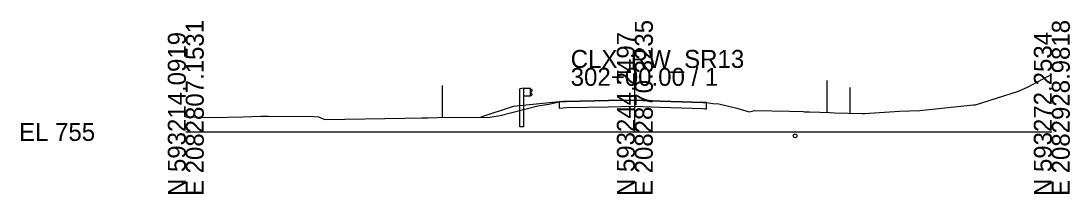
# Model space of a CAD drawing. Extents: x -26 to 2138, y -10 to 4518.
# Drawn here: x -25.7 to 137.8, y 1490.3 to 1517.3 of the extents above; entities that cross this region are included whole.
import ezdxf

# ---------------------------------------------------------------- set-up
doc = ezdxf.new("R2010")
doc.units = 0
for name, color, linetype in [('GK_Cells', 7, 'Continuous'), ('MD_X_Asphalt_Pavement', 7, 'Continuous'), ('RD_P_Cells', 7, 'Continuous'), ('RW_P_Esmt_SH', 7, 'Continuous'), ('RW_X_Esmt_SH', 7, 'Continuous'), ('UT_X_Water', 7, 'Continuous'), ('XS_P_Finished_Grade', 7, 'Continuous'), ('XS_X_Ground_Line', 7, 'Continuous')]:
    doc.layers.add(name, color=color, linetype=linetype)

msp = doc.modelspace()

# ---------------------------------------------------------------- linework, layer by layer
at = {"layer": 'GK_Cells'}
for p, q in [((70, 1500), (70, 1510)), ((0, 1500), (70, 1500)), ((70, 1500), (135, 1500))]:
    msp.add_line(p, q, dxfattribs=at)
at = {"layer": 'MD_X_Asphalt_Pavement'}
msp.add_lwpolyline([(58.83, 1504.74), (58.21, 1504.69), (58.21, 1503.73), (58.83, 1503.78), (59.27, 1503.8), (65.9, 1503.94), (69.89, 1504.02), (73.96, 1503.86), (80.6, 1503.64), (80.91, 1503.63), (81.15, 1503.62), (81.15, 1504.58), (80.91, 1504.59), (80.6, 1504.6), (73.96, 1504.82), (69.89, 1504.97), (65.9, 1504.9), (59.27, 1504.76), (58.83, 1504.74)], dxfattribs=at)
at = {"layer": 'RD_P_Cells'}
for p, q in [((52.1, 1506.73), (52.05, 1506.71)), ((52.05, 1500.81), (52.05, 1506.71)), ((52.64, 1506.81), (52.1, 1506.73)), ((52.72, 1506.77), (52.64, 1506.81)), ((53.72, 1506.77), (52.72, 1506.77)), ((52.72, 1500.81), (52.72, 1506.77)), ((53.72, 1505.58), (53.72, 1506.77)), ((53.81, 1506.67), (53.72, 1506.68)), ((53.73, 1506.17), (53.73, 1506.22)), ((53.73, 1506.13), (53.73, 1506.17)), ((53.76, 1506.28), (53.97, 1506.43)), ((53.97, 1506.56), (53.81, 1506.67)), ((53.72, 1505.58), (52.72, 1505.58)), ((53.72, 1505.66), (53.81, 1505.68)), ((53.97, 1505.92), (53.76, 1506.06)), ((53.81, 1505.68), (53.97, 1505.79)), ((52.72, 1500.81), (52.05, 1500.81))]:
    msp.add_line(p, q, dxfattribs=at)
for points in [[(53.74, 1506.23), (53.74, 1506.11), (53.73, 1506.11), (53.73, 1506.23)], [(53.74, 1506.2), (53.74, 1506.14), (53.76, 1506.14), (53.76, 1506.2)]]:
    msp.add_lwpolyline(points, close=True, dxfattribs=at)
for centre, start, end in [((53.81, 1506.22), 124.962, 180), ((53.92, 1506.49), 304.962, 54.7677), ((53.81, 1506.13), 180, 235.038), ((53.92, 1505.86), 304.962, 54.7677)]:
    msp.add_arc(centre, 0.0781, start, end, dxfattribs=at)
at = {"layer": 'RW_P_Esmt_SH'}
msp.add_line((103.56, 1502.94), (103.56, 1506.94), dxfattribs=at)
at = {"layer": 'RW_X_Esmt_SH'}
for p, q in [((100, 1503.05), (100, 1508.05)), ((40, 1502.24), (40, 1507.24))]:
    msp.add_line(p, q, dxfattribs=at)
at = {"layer": 'UT_X_Water'}
msp.add_circle((95, 1499.4), 0.3, dxfattribs=at)
at = {"layer": 'XS_P_Finished_Grade'}
for p, q in [((58.21, 1504.69), (51.05, 1503.97)), ((51.05, 1503.97), (46, 1502.29))]:
    msp.add_line(p, q, dxfattribs=at)
at = {"layer": 'XS_X_Ground_Line'}
msp.add_lwpolyline([(0, 1502.38), (1.9, 1502.3), (4.01, 1502.26), (8.93, 1502.36), (11.7, 1502.45), (12.88, 1502.46), (19.98, 1502.43), (20.67, 1502.35), (21.65, 1501.93), (34.16, 1502.14), (36.73, 1502.19), (37.13, 1502.19), (37.71, 1502.2), (39.2, 1502.23), (47.4, 1502.3), (49, 1502.55), (50.61, 1502.96), (54.9, 1504.08), (56.58, 1504.34), (58.21, 1504.69), (58.83, 1504.74), (59.27, 1504.76), (65.9, 1504.9), (69.89, 1504.97), (73.96, 1504.82), (80.6, 1504.6), (80.91, 1504.59), (81.15, 1504.58), (82.16, 1504.43), (83.09, 1504.41), (85.9, 1503.69), (87.8, 1503.13), (88.3, 1503.25), (88.64, 1503.33), (94.13, 1503.23), (96.25, 1503.17), (96.44, 1503.16), (97.24, 1503.14), (100.43, 1503.04), (101.15, 1503.01), (105.45, 1502.88), (105.74, 1502.86), (105.78, 1502.86), (111.25, 1503.24), (114.43, 1503.36), (121.31, 1504.07), (122.79, 1504.24), (123.1, 1504.22), (129.82, 1506.37), (131.34, 1507.03), (135, 1509.01)], dxfattribs=at)

# ---------------------------------------------------------------- texts
msp.add_text('-', height=0.0001).set_placement((0, 1500))
at = {"layer": 'GK_Cells'}
for s, p in [('E 2082807.1531', (2.8, 1490)), ('E 2082870.3235', (72.8, 1490)), ('E 2082928.9818', (137.8, 1490)), ('N 593214.0919', (0, 1490)), ('N 593244.2497', (70, 1490)), ('N 593272.2534', (135, 1490))]:
    msp.add_text(s, height=2.8, rotation=90, dxfattribs=at).set_placement(p)
for s, p in [('CLX_RW_SR13', (60, 1510)), ('302+00.00 / 1', (60, 1507.2)), ('EL 755', (-26, 1498.6))]:
    msp.add_text(s, height=2.8, dxfattribs=at).set_placement(p)

doc.saveas('drawing.dxf')
